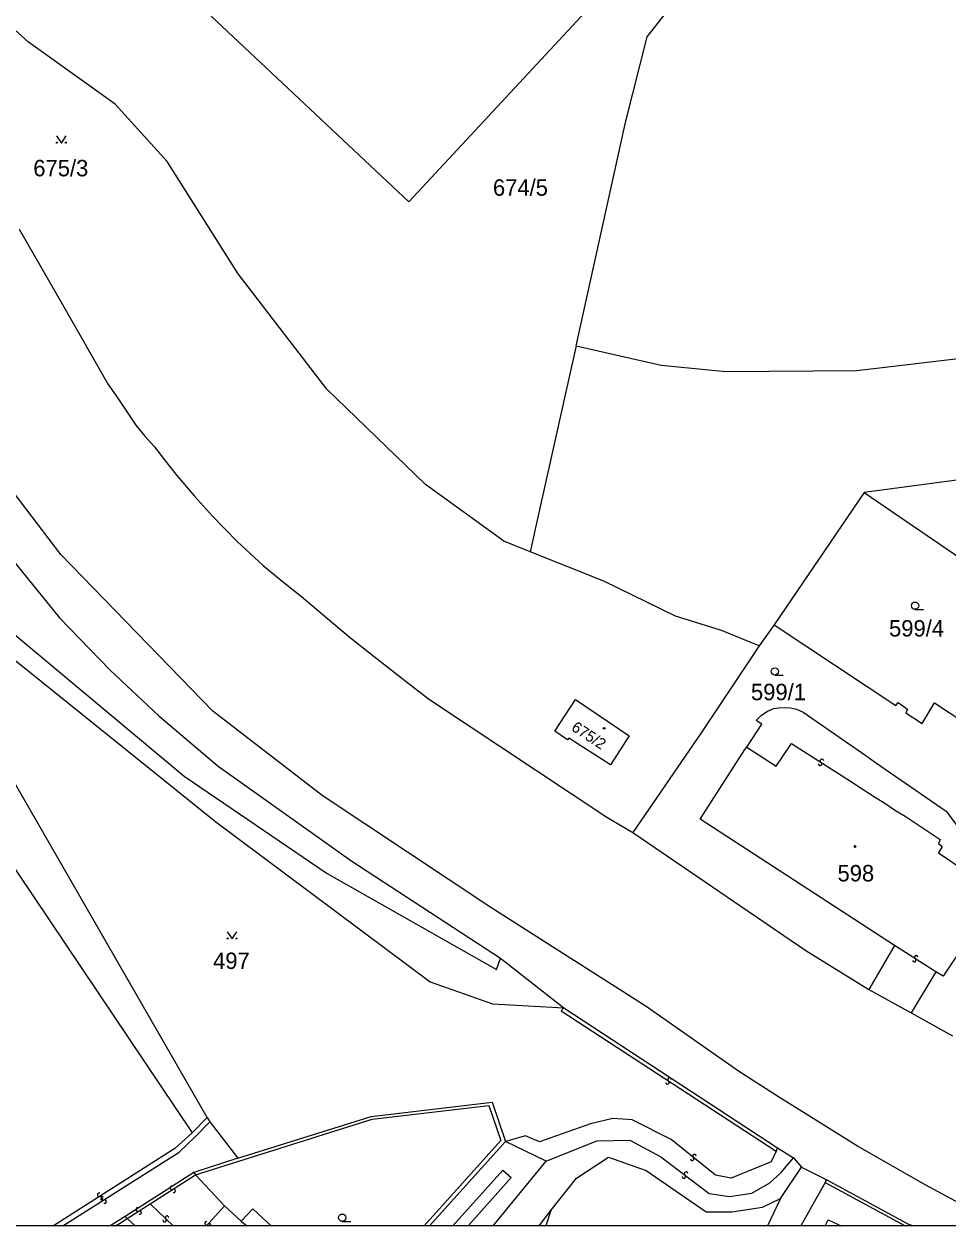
# Model space of a CAD drawing. Extents: x -600391 to -599491, y -1160176 to -1159402.
# Drawn here: x -599692.2 to -599596.7, y -1160176.1 to -1160051.8 of the extents above; entities that cross this region are included whole.
import ezdxf

# ---------------------------------------------------------------- set-up
doc = ezdxf.new("R2010")
doc.units = 0
for name, color, linetype in [('Level 1', 7, 'Continuous'), ('Level 13', 7, 'Continuous'), ('Level 3', 7, 'Continuous'), ('Level 4', 7, 'Continuous'), ('Level 5', 7, 'Continuous'), ('Vrstva 63', 7, 'Continuous')]:
    doc.layers.add(name, color=color, linetype=linetype)

msp = doc.modelspace()

# ---------------------------------------------------------------- linework, layer by layer
at = {"layer": 'Level 1'}
for p, q in [((-599642.41, -1160167.34), (-599650.27, -1160176.08)), ((-599643.71, -1160176.08), (-599638.23, -1160169.38)), ((-599609.38, -1160171.58), (-599611.89, -1160176.08)), ((-599609.26, -1160171.29), (-599600.44, -1160176.08)), ((-599638.93, -1160176.08), (-599637.72, -1160174.47)), ((-599681.76, -1160175.09), (-599683.31, -1160176.08)), ((-599682.57, -1160176.08), (-599682.35, -1160175.83))]:
    msp.add_line(p, q, dxfattribs=at)
for points in [[(-599591.16, -1160176.08), (-599598.97, -1160171.85), (-599606.03, -1160167.81), (-599614.1, -1160162.79), (-599618.32, -1160160.08), (-599627.86, -1160153.38), (-599643.84, -1160143.22), (-599661.38, -1160131.54), (-599672.7, -1160122.83), (-599688.39, -1160106.63), (-599694.45, -1160098.7), (-599700.67, -1160088.64), (-599704.82, -1160081.15), (-599706.43, -1160078.31), (-599708.41, -1160074.82), (-599715.88, -1160064.05), (-599722.37, -1160056.97), (-599739.93, -1160040.41), (-599768.82, -1160013.48), (-599771.3, -1160011), (-599773.09, -1160009.38), (-599799.04, -1159987.23)], [(-599591.16, -1160176.08), (-599598.97, -1160171.85), (-599606.03, -1160167.81), (-599614.1, -1160162.79), (-599618.32, -1160160.08), (-599627.86, -1160153.38), (-599643.84, -1160143.22), (-599661.38, -1160131.54), (-599672.7, -1160122.83), (-599688.39, -1160106.63), (-599694.45, -1160098.7), (-599700.67, -1160088.64), (-599704.82, -1160081.15), (-599706.43, -1160078.31), (-599708.41, -1160074.82), (-599715.88, -1160064.05), (-599722.37, -1160056.97), (-599739.93, -1160040.41), (-599768.82, -1160013.48), (-599771.3, -1160011), (-599773.09, -1160009.38), (-599799.04, -1159987.23)], [(-599672.86, -1160050.94), (-599652.4, -1160070.14), (-599628.22, -1160044.09), (-599648.83, -1160025.17)], [(-599635.13, -1160085.06), (-599630, -1160061.95), (-599627.78, -1160053.1), (-599611.57, -1160032.42)], [(-599639.86, -1160106.35), (-599642.58, -1160105.26), (-599650.69, -1160099.39), (-599660.9, -1160089.51), (-599670.05, -1160077.58), (-599677.41, -1160065.97), (-599682.78, -1160060.04), (-599691.73, -1160053.65), (-599707.8, -1160039.08)], [(-599635.13, -1160085.06), (-599626.32, -1160087.03), (-599619.65, -1160087.7), (-599606.09, -1160087.6), (-599592.68, -1160086.01), (-599574.93, -1160082.96), (-599566.24, -1160080.68), (-599557.68, -1160077.83), (-599549.28, -1160074.49), (-599541.18, -1160070.63), (-599533.36, -1160066.17), (-599512.98, -1160053.83)], [(-599692.71, -1160072.98), (-599688.1, -1160081.01), (-599683.5, -1160089.04), (-599682.76, -1160090.11), (-599682.02, -1160091.18), (-599681.33, -1160092.22), (-599680.64, -1160093.26), (-599679.7, -1160094.39), (-599678.73, -1160095.5), (-599677.57, -1160096.99), (-599676.4, -1160098.47), (-599674.59, -1160100.59), (-599672.72, -1160102.65), (-599670.18, -1160105.29), (-599667.49, -1160107.78), (-599665.5, -1160109.37), (-599663.5, -1160110.96), (-599661.95, -1160112.29), (-599660.39, -1160113.61), (-599658.45, -1160115.23), (-599656.49, -1160116.81), (-599653.44, -1160119.18), (-599650.39, -1160121.56), (-599631.94, -1160133.78), (-599629.27, -1160135.39)], [(-599712.68, -1160076.43), (-599699.62, -1160098.24), (-599693.69, -1160106.83), (-599688.53, -1160113.18), (-599683.31, -1160118.59), (-599678.26, -1160123.31), (-599672.15, -1160128.51), (-599658.31, -1160138.33), (-599642.94, -1160148.37)], [(-599635.13, -1160085.06), (-599635.23, -1160085.5), (-599638.93, -1160102.15), (-599639.86, -1160106.35)], [(-599549.47, -1160092.84), (-599559.04, -1160094.06), (-599605.34, -1160100.2)], [(-599605.34, -1160100.2), (-599614.63, -1160113.89)], [(-599605.34, -1160100.2), (-599583.16, -1160115.36)], [(-599616.18, -1160116.08), (-599620.08, -1160114.5), (-599624.85, -1160113), (-599632.25, -1160109.4), (-599639.86, -1160106.35)], [(-599614.63, -1160113.89), (-599616.18, -1160116.08)], [(-599614.63, -1160113.89), (-599602.06, -1160122.26), (-599601.81, -1160121.94), (-599600.85, -1160122.64), (-599601.01, -1160122.99), (-599599.35, -1160124.1), (-599598.05, -1160121.98), (-599594.94, -1160124.04), (-599583.16, -1160115.36)], [(-599616.18, -1160116.08), (-599622.18, -1160125.07), (-599629.27, -1160135.39)], [(-599635.19, -1160121.61), (-599629.62, -1160125.38), (-599631.56, -1160128.39), (-599635.86, -1160125.61), (-599636, -1160125.81), (-599637.33, -1160124.89), (-599635.19, -1160121.61)], [(-599617.48, -1160126.56), (-599615.93, -1160124.16), (-599616.49, -1160123.78), (-599615.95, -1160123.25), (-599615.37, -1160122.88), (-599614.71, -1160122.56), (-599614.17, -1160122.48), (-599613.6, -1160122.46), (-599612.94, -1160122.48), (-599612.33, -1160122.64), (-599611.65, -1160122.93), (-599605.15, -1160127.41), (-599604.16, -1160128.13), (-599596.85, -1160133.17), (-599590.95, -1160141.11), (-599588.93, -1160142.46), (-599590.09, -1160144.19), (-599592.21, -1160142.82)], [(-599602.18, -1160147.08), (-599622.28, -1160134), (-599617.68, -1160126.8), (-599617.48, -1160126.56)], [(-599629.27, -1160135.39), (-599611.35, -1160147.6), (-599604.86, -1160151.61)], [(-599703.45, -1160142.7), (-599694.53, -1160137.07), (-599674.81, -1160166.46)], [(-599592.21, -1160142.82), (-599597.16, -1160150.24), (-599597.92, -1160149.79)], [(-599602.18, -1160147.08), (-599604.86, -1160151.61)], [(-599642.94, -1160148.37), (-599636.4, -1160153.52)], [(-599597.92, -1160149.79), (-599600.49, -1160154.02)], [(-599604.86, -1160151.61), (-599600.49, -1160154.02)], [(-599636.4, -1160153.52), (-599614.29, -1160168.01)], [(-599600.49, -1160154.02), (-599596.2, -1160156.4)], [(-599670.09, -1160169.08), (-599656.32, -1160164.74), (-599643.81, -1160163.29), (-599642.41, -1160167.34)], [(-599674.81, -1160166.46), (-599673.27, -1160164.85)], [(-599673.27, -1160164.85), (-599672.98, -1160165.32)], [(-599672.98, -1160165.32), (-599670.09, -1160169.08)], [(-599638.23, -1160169.38), (-599642.41, -1160167.34)], [(-599614.29, -1160168.01), (-599612.65, -1160169.02)], [(-599670.09, -1160169.08), (-599674.65, -1160170.54)], [(-599637.72, -1160174.47), (-599635.07, -1160171.14), (-599631.76, -1160168.97), (-599627.89, -1160170.35), (-599621.66, -1160174.61), (-599619.03, -1160174.62), (-599615.86, -1160174.12), (-599614, -1160173.23)], [(-599612.65, -1160169.02), (-599611.81, -1160170.01)], [(-599674.65, -1160170.54), (-599681.76, -1160175.09)], [(-599674.65, -1160170.54), (-599674.49, -1160170.79)], [(-599674.49, -1160170.79), (-599671.47, -1160173.99)], [(-599614, -1160173.23), (-599611.81, -1160170.01)], [(-599611.81, -1160170.01), (-599609.26, -1160171.29)], [(-599609.26, -1160171.29), (-599609.38, -1160171.58)], [(-599671.47, -1160173.99), (-599669.74, -1160175.58)], [(-599669.74, -1160175.58), (-599668.56, -1160174.31), (-599667.49, -1160175.31), (-599666.65, -1160176.08)], [(-599682.35, -1160175.83), (-599681.54, -1160175.3)], [(-599681.54, -1160175.3), (-599681.76, -1160175.09)]]:
    msp.add_lwpolyline(points, dxfattribs=at)
at = {"layer": 'Level 13'}
for centre, start, end in [((-599609.9, -1160128.27), 184.5657, 57.1557), ((-599609.7, -1160127.97), 4.7802, 236.8782), ((-599600.15, -1160148.59), 184.9102, 57.0082), ((-599599.95, -1160148.29), 4.6958, 237.2858), ((-599625.66, -1160161.23), 184.0194, 56.6094), ((-599625.46, -1160160.93), 4.2339, 236.3319), ((-599623.12, -1160169.13), 178.5614, 50.6593), ((-599622.88, -1160168.85), 358.3469, 230.9369), ((-599623.97, -1160170.97), 180.0512, 52.6412), ((-599623.75, -1160170.67), 0.2657, 232.3637), ((-599676.92, -1160172.13), 70.0024, 302.1004), ((-599676.72, -1160172.45), 249.788, 122.378), ((-599684.44, -1160172.86), 69.663, 302.253), ((-599684.24, -1160173.18), 249.8774, 121.9754), ((-599684.08, -1160173.24), 69.8368, 301.9348), ((-599683.88, -1160173.56), 249.6224, 122.2124), ((-599680.45, -1160174.38), 69.9373, 302.0353), ((-599680.25, -1160174.7), 249.7228, 122.3128), ((-599677.68, -1160175.48), 173.1822, 45.2802), ((-599677.42, -1160175.22), 352.9677, 225.5577), ((-599673.33, -1160175.8), 85.6746, 317.7726), ((-599673.05, -1160176.04), 348.8577, 138.0501), ((-599600.57, -1160176.15), 22.3318, 157.6682)]:
    msp.add_arc(centre, 0.184, start, end, dxfattribs=at)
at = {"layer": 'Level 3'}
for p, q in [((-599609.38, -1160171.58), (-599601.09, -1160176.08)), ((-599614, -1160173.23), (-599615.32, -1160176.08)), ((-599676.8, -1160176.08), (-599679.16, -1160173.78)), ((-599673.33, -1160176.08), (-599671.47, -1160173.99)), ((-599637.72, -1160174.47), (-599638.26, -1160176.08)), ((-599682.74, -1160176.08), (-599682.35, -1160175.83)), ((-599680.73, -1160176.08), (-599681.54, -1160175.3)), ((-599669.74, -1160175.58), (-599669.18, -1160176.08))]:
    msp.add_line(p, q, dxfattribs=at)
for points in [[(-599714.29, -1160087.48), (-599694.08, -1160114.16), (-599675.64, -1160129.55), (-599660.86, -1160139.62), (-599643.36, -1160149.55), (-599642.94, -1160148.37)], [(-599673.27, -1160164.85), (-599715.17, -1160092.05), (-599694.46, -1160116.5), (-599672.38, -1160134.27), (-599650.22, -1160150.84), (-599643.75, -1160153.09), (-599636.4, -1160153.52)], [(-599617.48, -1160126.56), (-599614.43, -1160128.52), (-599612.85, -1160126.17), (-599606.75, -1160130.07), (-599605.74, -1160130.72), (-599604.25, -1160131.69), (-599603.3, -1160132.28), (-599602.1, -1160133.1), (-599601.11, -1160133.7), (-599597.46, -1160136.11), (-599597.66, -1160136.51), (-599597.27, -1160136.83), (-599597.66, -1160137.48), (-599595, -1160139.29), (-599595.75, -1160140.48), (-599592.21, -1160142.82)], [(-599597.92, -1160149.79), (-599602.18, -1160147.08)], [(-599636.4, -1160153.52), (-599636.66, -1160153.83), (-599614.45, -1160168.33)], [(-599674.49, -1160170.79), (-599656.21, -1160165.03), (-599644.16, -1160163.62), (-599642.9, -1160167.23), (-599650.84, -1160176.08)], [(-599688.18, -1160176.08), (-599676.16, -1160168.43), (-599674.5, -1160166.86), (-599672.98, -1160165.32)], [(-599614.45, -1160168.33), (-599614.95, -1160169.44), (-599619.09, -1160171.13), (-599620.7, -1160170.84), (-599625.3, -1160167.14), (-599629.33, -1160165.11), (-599631.31, -1160164.96), (-599633.63, -1160165.53), (-599638.92, -1160167.38), (-599640.34, -1160166.75), (-599642.41, -1160167.34)], [(-599674.81, -1160166.46), (-599676.6, -1160168.08), (-599689.15, -1160176.08)], [(-599638.23, -1160169.38), (-599632.99, -1160167.29), (-599629.56, -1160167.22), (-599626.36, -1160168.92), (-599621.35, -1160172.71), (-599619.26, -1160173.03), (-599616.94, -1160172.69), (-599615.1, -1160171.62), (-599613.91, -1160170.55), (-599612.65, -1160169.02)], [(-599614.29, -1160168.01), (-599614.45, -1160168.33)], [(-599679.16, -1160173.78), (-599674.49, -1160170.79)], [(-599647.88, -1160176.08), (-599642.7, -1160170.3), (-599641.84, -1160171.08), (-599646.28, -1160176.08)], [(-599681.54, -1160175.3), (-599679.16, -1160173.78)], [(-599609.38, -1160176.08), (-599609.04, -1160175.43), (-599607.7, -1160176.08)]]:
    msp.add_lwpolyline(points, dxfattribs=at)
at = {"layer": 'Level 5'}
for p, q in [((-599600.07, -1160112.3), (-599599.2, -1160112.3)), ((-599614.57, -1160119.1), (-599613.7, -1160119.1)), ((-599659.3, -1160175.6), (-599658.43, -1160175.6))]:
    msp.add_line(p, q, dxfattribs=at)
for points in [[(-599688.85, -1160063.33), (-599688.35, -1160064.08), (-599687.85, -1160063.33)], [(-599671.2, -1160145.64), (-599670.7, -1160146.39), (-599670.2, -1160145.64)]]:
    msp.add_lwpolyline(points, dxfattribs=at)
for centre, radius in [((-599688.8, -1160064.03), 0.05), ((-599687.9, -1160064.03), 0.05), ((-599600.07, -1160111.92), 0.375), ((-599614.57, -1160118.72), 0.375), ((-599632.22, -1160124.61), 0.09), ((-599632.22, -1160124.61), 0.0521), ((-599606.28, -1160136.83), 0.09), ((-599606.28, -1160136.83), 0.0521), ((-599671.15, -1160146.34), 0.05), ((-599670.25, -1160146.34), 0.05), ((-599659.3, -1160175.22), 0.375)]:
    msp.add_circle(centre, radius, dxfattribs=at)
at = {"layer": 'Vrstva 63'}
msp.add_lwpolyline([(-600391.01, -1159401.77), (-599490.77, -1159401.77), (-599490.77, -1160176.08), (-600391.01, -1160176.08)], close=True, dxfattribs=at)

# ---------------------------------------------------------------- texts
at = {"layer": 'Level 4'}
for s, p in [('675/3', (-599691.25, -1160067.51)), ('674/5', (-599643.72, -1160069.52)), ('599/4', (-599602.76, -1160115.11)), ('599/1', (-599617.04, -1160121.7)), ('598', (-599608.09, -1160140.44)), ('497', (-599672.66, -1160149.5))]:
    msp.add_text(s, height=1.7, dxfattribs=at).set_placement(p)
msp.add_text('675/2', height=1.14, rotation=326.7, dxfattribs=at).set_placement((-599635.7, -1160124.76))

doc.saveas('drawing.dxf')
